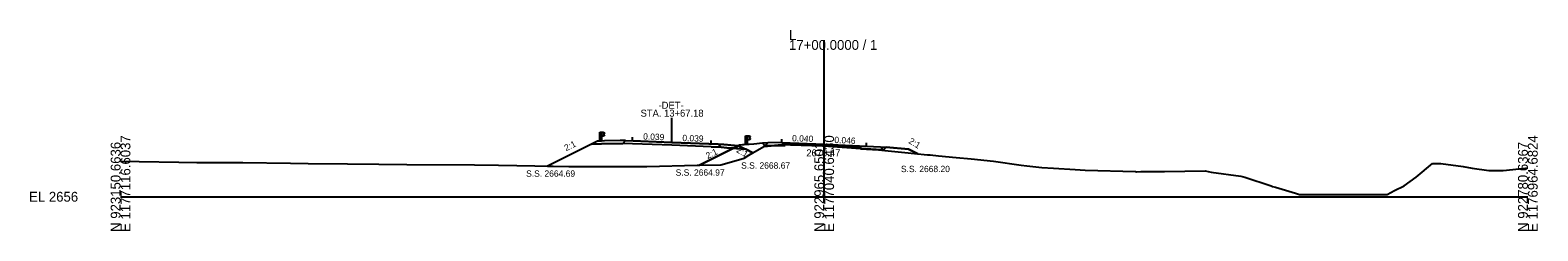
# Model space of a CAD drawing. Extents: x -26 to 1403, y -10 to 9563.
# Drawn here: x -25.7 to 402.8, y 6990.3 to 7047.4 of the extents above; entities that cross this region are included whole.
import ezdxf

# ---------------------------------------------------------------- set-up
doc = ezdxf.new("R2010")
doc.units = 0
for name, color, linetype in [('Exist Cross Section Cell', 7, 'Continuous'), ('Exist XS Center Line Elevation Label', 7, 'Continuous'), ('Exist XS Ground Line', 7, 'Continuous'), ('Prop XS Ditch Slope Text', 7, 'Continuous'), ('Prop XS Dump Level', 7, 'Continuous'), ('Prop XS Earthwork Shape', 7, 'Continuous'), ('Prop XS EOT Tick Mark', 7, 'Continuous'), ('Prop XS Finish Grade', 7, 'Continuous'), ('Prop XS Finish Grade Earthwork', 7, 'Continuous'), ('Prop XS Finish Grade Paved Shoulder', 7, 'Continuous'), ('Prop XS Finish Grade Pavement', 7, 'Continuous'), ('Prop XS Guardrail', 7, 'Continuous'), ('Prop XS Pvmt Edge Slope', 7, 'Continuous'), ('Prop XS SE Text', 7, 'Continuous'), ('Prop XS Shoulder Borrow Shape', 7, 'Continuous'), ('Prop XS Side Slope Text', 7, 'Continuous'), ('Prop XS SS Elevation Text', 7, 'Continuous'), ('Prop XS Subgrade Earthwork', 7, 'Continuous'), ('Prop XS Vertical Lines', 7, 'Continuous'), ('Prop XS Wedging', 7, 'Continuous')]:
    doc.layers.add(name, color=color, linetype=linetype)

msp = doc.modelspace()

# ---------------------------------------------------------------- linework, layer by layer
at = {"layer": 'Exist Cross Section Cell'}
for p, q in [((200, 7000), (200, 7044.56)), ((0, 7000), (200, 7000)), ((200, 7000), (400, 7000))]:
    msp.add_line(p, q, dxfattribs=at)
at = {"layer": 'Exist XS Ground Line'}
for p, q in [((176.35, 7010.73), (177.25, 7011.01)), ((177.25, 7011.01), (178.55, 7011.85)), ((178.55, 7011.85), (179.7, 7012.51)), ((179.7, 7012.51), (182.8, 7014.31)), ((182.8, 7014.31), (187.98, 7014.79)), ((187.98, 7014.79), (188.9, 7014.85)), ((188.9, 7014.85), (190.43, 7014.8)), ((190.43, 7014.8), (199.5, 7014.5)), ((199.5, 7014.5), (200, 7014.47)), ((200, 7014.47), (201.25, 7014.38)), ((201.25, 7014.38), (210.33, 7013.71)), ((210.33, 7013.71), (214.75, 7013.45)), ((214.75, 7013.45), (218.22, 7013.06)), ((218.22, 7013.06), (221.99, 7012.63)), ((221.99, 7012.63), (229.35, 7011.95)), ((229.35, 7011.95), (230.11, 7011.9)), ((230.11, 7011.9), (232.48, 7011.68)), ((232.48, 7011.68), (237.49, 7011.14)), ((237.49, 7011.14), (241.81, 7010.78)), ((0, 7010.07), (5.31, 7009.99)), ((5.31, 7009.99), (16.57, 7009.81)), ((16.57, 7009.81), (21.65, 7009.76)), ((21.65, 7009.76), (34.76, 7009.71)), ((34.76, 7009.71), (48.33, 7009.52)), ((48.33, 7009.52), (53.32, 7009.5)), ((53.32, 7009.5), (64.54, 7009.33)), ((64.54, 7009.33), (73.43, 7009.24)), ((73.43, 7009.24), (81.36, 7009.15)), ((81.36, 7009.15), (100.56, 7009.03)), ((100.56, 7009.03), (107.41, 7008.96)), ((107.41, 7008.96), (122.93, 7008.67)), ((122.93, 7008.67), (127.45, 7008.6)), ((127.45, 7008.6), (129.72, 7008.63)), ((129.72, 7008.63), (149.62, 7008.56)), ((149.62, 7008.56), (163.85, 7008.96)), ((163.85, 7008.96), (170.66, 7009.09)), ((170.66, 7009.09), (176.35, 7010.73)), ((241.81, 7010.78), (248.15, 7010.13)), ((248.15, 7010.13), (256.03, 7008.99)), ((256.03, 7008.99), (257.59, 7008.79)), ((257.59, 7008.79), (261.85, 7008.34)), ((261.85, 7008.34), (265.15, 7008.15)), ((265.15, 7008.15), (271.33, 7007.79)), ((271.33, 7007.79), (274.16, 7007.6)), ((274.16, 7007.6), (288.49, 7007.14)), ((288.49, 7007.14), (288.8, 7007.13)), ((288.8, 7007.13), (289.97, 7007.14)), ((289.97, 7007.14), (296.76, 7007.21)), ((296.76, 7007.21), (308.3, 7007.34)), ((308.3, 7007.34), (309.94, 7007.03)), ((309.94, 7007.03), (318.44, 7005.86)), ((368.27, 7005.58), (372.89, 7009.44)), ((372.89, 7009.44), (375.26, 7009.44)), ((375.26, 7009.44), (381.63, 7008.59)), ((381.63, 7008.59), (384.17, 7008.11)), ((384.17, 7008.11), (388.94, 7007.5)), ((388.94, 7007.5), (393, 7007.46)), ((393, 7007.46), (399.36, 7008.14)), ((399.36, 7008.14), (400, 7008.19)), ((318.44, 7005.86), (319.58, 7005.56)), ((319.58, 7005.56), (327.01, 7003.06)), ((327.01, 7003.06), (327.46, 7002.93)), ((327.46, 7002.93), (328.25, 7002.69)), ((328.25, 7002.69), (333.96, 7001.02)), ((362.11, 7001.76), (364.86, 7003.08)), ((364.86, 7003.08), (368.27, 7005.58)), ((333.96, 7001.02), (335.14, 7000.67)), ((335.14, 7000.67), (347.82, 7000.65)), ((347.82, 7000.65), (353.68, 7000.64)), ((353.68, 7000.64), (359.98, 7000.63)), ((359.98, 7000.63), (362.11, 7001.76))]:
    msp.add_line(p, q, dxfattribs=at)
at = {"layer": 'Prop XS Dump Level'}
for p, q in [((143.54, 7015.98), (156.68, 7015.46)), ((156.68, 7015.46), (145.54, 7015.9)), ((169.82, 7014.94), (156.68, 7015.46)), ((156.68, 7015.46), (169.82, 7014.94)), ((188, 7015.4), (200, 7014.91)), ((200, 7014.91), (212, 7014.36))]:
    msp.add_line(p, q, dxfattribs=at)
at = {"layer": 'Prop XS Earthwork Shape'}
for p, q in [((142.74, 7015.18), (136.74, 7015.05)), ((145.54, 7015.07), (142.74, 7015.18)), ((182.43, 7015.19), (180, 7014.99)), ((183.15, 7014.46), (182.43, 7015.19)), ((133.9, 7014.99), (121.32, 7008.7)), ((136.74, 7015.05), (133.9, 7014.99)), ((156.68, 7014.63), (145.54, 7015.07)), ((167.83, 7014.19), (156.68, 7014.63)), ((164.56, 7008.97), (174.21, 7013.79)), ((174.21, 7013.79), (164.56, 7008.97)), ((174.21, 7013.79), (164.56, 7008.97)), ((170.69, 7014.08), (167.83, 7014.19)), ((172.3, 7013.95), (170.69, 7014.08)), ((174.21, 7013.79), (172.3, 7013.95)), ((177.73, 7013.51), (174.21, 7013.79)), ((177.73, 7013.51), (174.21, 7013.79)), ((175.96, 7014.67), (175.58, 7014.48)), ((175.58, 7014.48), (175.83, 7014.46)), ((175.83, 7014.46), (177.73, 7013.51)), ((176.35, 7010.73), (177.25, 7011.01)), ((176.35, 7010.73), (177.25, 7011.01)), ((177.25, 7011.01), (178.55, 7011.85)), ((177.25, 7011.01), (178.55, 7011.85)), ((179.72, 7012.52), (177.73, 7013.51)), ((179.72, 7012.52), (177.73, 7013.51)), ((177.73, 7013.51), (179.72, 7012.52)), ((178.55, 7011.85), (179.7, 7012.51)), ((178.55, 7011.85), (179.7, 7012.51)), ((179.7, 7012.51), (179.72, 7012.52)), ((179.7, 7012.51), (179.72, 7012.52)), ((179.72, 7012.52), (182.8, 7014.31)), ((182.8, 7014.31), (184.85, 7014.5)), ((184.85, 7014.5), (183.15, 7014.46)), ((216.87, 7013.3), (215.48, 7013.37)), ((215.48, 7013.37), (218.22, 7013.06)), ((217.62, 7014.05), (216.87, 7013.3)), ((223.99, 7013.54), (217.62, 7014.05)), ((218.22, 7013.06), (221.99, 7012.63)), ((221.99, 7012.63), (226.66, 7012.2)), ((226.66, 7012.2), (223.99, 7013.54)), ((121.32, 7008.7), (122.93, 7008.67)), ((122.93, 7008.67), (127.45, 7008.6)), ((127.45, 7008.6), (129.72, 7008.63)), ((129.72, 7008.63), (149.62, 7008.56)), ((149.62, 7008.56), (163.85, 7008.96)), ((163.85, 7008.96), (164.56, 7008.97)), ((164.56, 7008.97), (170.66, 7009.09)), ((164.56, 7008.97), (170.66, 7009.09)), ((170.66, 7009.09), (176.35, 7010.73)), ((170.66, 7009.09), (176.35, 7010.73))]:
    msp.add_line(p, q, dxfattribs=at)
msp.add_lwpolyline([(180, 7014.99), (178.14, 7014.85), (177.64, 7014.81), (175.96, 7014.67)], dxfattribs=at)
at = {"layer": 'Prop XS EOT Tick Mark'}
for p, q in [((145.54, 7015.9), (145.54, 7016.9)), ((167.83, 7015.02), (167.83, 7016.02)), ((188, 7015.4), (188, 7016.4)), ((212, 7014.36), (212, 7015.36))]:
    msp.add_line(p, q, dxfattribs=at)
at = {"layer": 'Prop XS Finish Grade'}
for p, q in [((143.54, 7015.98), (141.97, 7015.95)), ((184, 7015.32), (182.43, 7015.19)), ((169.82, 7014.94), (171.43, 7014.81)), ((216, 7014.18), (217.62, 7014.05))]:
    msp.add_line(p, q, dxfattribs=at)
at = {"layer": 'Prop XS Finish Grade Earthwork'}
for p, q in [((135.54, 7015.81), (133.9, 7014.99)), ((137.54, 7015.86), (135.54, 7015.81)), ((141.97, 7015.95), (137.54, 7015.86)), ((182.43, 7015.19), (180, 7014.99)), ((133.9, 7014.99), (121.32, 7008.7)), ((175.96, 7014.67), (164.56, 7008.97)), ((171.43, 7014.81), (175.83, 7014.46)), ((175.83, 7014.46), (177.73, 7013.51)), ((180, 7014.99), (175.96, 7014.67)), ((177.73, 7013.51), (179.72, 7012.52)), ((217.62, 7014.05), (223.99, 7013.54)), ((223.99, 7013.54), (226.66, 7012.2))]:
    msp.add_line(p, q, dxfattribs=at)
at = {"layer": 'Prop XS Finish Grade Paved Shoulder'}
for p, q in [((188, 7015.4), (184, 7015.32)), ((212, 7014.36), (216, 7014.18))]:
    msp.add_line(p, q, dxfattribs=at)
at = {"layer": 'Prop XS Finish Grade Pavement'}
for p, q in [((143.54, 7015.98), (156.68, 7015.46)), ((156.68, 7015.46), (169.82, 7014.94)), ((188, 7015.4), (200, 7014.91)), ((200, 7014.91), (212, 7014.36))]:
    msp.add_line(p, q, dxfattribs=at)
at = {"layer": 'Prop XS Guardrail'}
for p, q in [((136.22, 7018.34), (136.72, 7018.34)), ((136.22, 7015.84), (136.22, 7018.34)), ((136.72, 7018.34), (137.22, 7018.34)), ((136.72, 7018.34), (136.72, 7015.84)), ((137.22, 7017.2), (136.72, 7017.2)), ((137.22, 7018.34), (137.51, 7018.14)), ((137.51, 7018.02), (137.22, 7017.82)), ((137.22, 7017.82), (137.22, 7017.72)), ((137.22, 7017.72), (137.51, 7017.52)), ((137.51, 7017.4), (137.22, 7017.2)), ((137.51, 7018.14), (137.54, 7018.08)), ((137.54, 7018.08), (137.51, 7018.02)), ((137.51, 7017.52), (137.54, 7017.46)), ((137.54, 7017.46), (137.51, 7017.4)), ((177.64, 7017.35), (178.14, 7017.35)), ((177.64, 7014.81), (177.64, 7017.35)), ((178.14, 7017.35), (178.64, 7017.35)), ((178.14, 7017.35), (178.14, 7014.85)), ((178.64, 7016.21), (178.14, 7016.21)), ((178.64, 7017.35), (178.93, 7017.15)), ((178.93, 7017.03), (178.64, 7016.83)), ((178.64, 7016.83), (178.64, 7016.73)), ((178.64, 7016.73), (178.93, 7016.53)), ((178.93, 7016.41), (178.64, 7016.21)), ((178.93, 7017.15), (178.96, 7017.09)), ((178.96, 7017.09), (178.93, 7017.03)), ((178.93, 7016.53), (178.96, 7016.47)), ((178.96, 7016.47), (178.93, 7016.41))]:
    msp.add_line(p, q, dxfattribs=at)
at = {"layer": 'Prop XS Pvmt Edge Slope'}
for p, q in [((143.54, 7015.98), (142.74, 7015.18)), ((184, 7015.32), (183.15, 7014.46)), ((169.82, 7014.94), (170.69, 7014.08)), ((216, 7014.18), (216.87, 7013.3))]:
    msp.add_line(p, q, dxfattribs=at)
at = {"layer": 'Prop XS Shoulder Borrow Shape'}
for p, q in [((135.54, 7015.81), (133.9, 7014.99)), ((136.74, 7015.05), (142.74, 7015.18)), ((141.97, 7015.95), (137.54, 7015.86)), ((143.54, 7015.98), (141.97, 7015.95)), ((142.74, 7015.18), (143.54, 7015.98)), ((133.9, 7014.99), (136.74, 7015.05)), ((171.43, 7014.81), (169.82, 7014.94)), ((169.82, 7014.94), (170.69, 7014.08)), ((170.69, 7014.08), (172.3, 7013.95)), ((175.58, 7014.48), (171.43, 7014.81)), ((172.3, 7013.95), (174.21, 7013.79)), ((174.21, 7013.79), (175.58, 7014.48))]:
    msp.add_line(p, q, dxfattribs=at)
msp.add_lwpolyline([(137.54, 7015.86), (136.72, 7015.84), (135.54, 7015.81)], dxfattribs=at)
at = {"layer": 'Prop XS Subgrade Earthwork'}
for p, q in [((142.74, 7015.18), (136.74, 7015.05)), ((145.54, 7015.07), (142.74, 7015.18)), ((183.15, 7014.46), (182.43, 7015.19)), ((136.74, 7015.05), (133.9, 7014.99)), ((156.68, 7014.63), (145.54, 7015.07)), ((167.83, 7014.19), (156.68, 7014.63)), ((167.83, 7014.19), (170.69, 7014.08)), ((170.69, 7014.08), (172.3, 7013.95)), ((172.3, 7013.95), (177.73, 7013.51)), ((188, 7014.56), (183.15, 7014.46)), ((188, 7014.56), (188.9, 7014.53)), ((188.9, 7014.53), (188.9, 7014.85)), ((210.33, 7013.6), (210.33, 7013.71)), ((210.33, 7013.6), (216.87, 7013.3)), ((216.87, 7013.3), (217.62, 7014.05))]:
    msp.add_line(p, q, dxfattribs=at)
at = {"layer": 'Prop XS Vertical Lines'}
msp.add_line((156.68, 7015.46), (156.68, 7022.46), dxfattribs=at)
at = {"layer": 'Prop XS Wedging'}
for p, q in [((187.98, 7014.79), (184.85, 7014.5)), ((184.85, 7014.5), (188, 7014.56)), ((188.9, 7014.85), (187.98, 7014.79)), ((188, 7014.56), (188.9, 7014.53)), ((188.9, 7014.53), (188.9, 7014.85)), ((214.75, 7013.45), (210.33, 7013.71)), ((210.33, 7013.71), (210.33, 7013.6)), ((210.33, 7013.6), (215.48, 7013.37)), ((215.48, 7013.37), (214.75, 7013.45))]:
    msp.add_line(p, q, dxfattribs=at)
msp.add_lwpolyline([(188.9, 7014.85), (188.9, 7015.16), (190.43, 7015.09), (199.5, 7014.73), (200, 7014.71), (200.55, 7014.69), (201.25, 7014.65), (210.33, 7014.2), (210.33, 7013.71), (201.25, 7014.38), (200.55, 7014.43), (200, 7014.47), (199.5, 7014.5), (190.43, 7014.8)], close=True, dxfattribs=at)
msp.add_lwpolyline([(188.9, 7014.85), (188.9, 7015.16), (190.43, 7015.09), (199.5, 7014.73), (200, 7014.71), (200.55, 7014.69), (201.25, 7014.65), (210.33, 7014.2), (210.33, 7013.71), (201.25, 7014.38), (200.55, 7014.43), (200, 7014.47), (199.5, 7014.5), (190.43, 7014.8)], close=True, dxfattribs=at)

# ---------------------------------------------------------------- texts
at = {"layer": 'Exist Cross Section Cell'}
for s, p in [('L', (190, 7044.56)), ('17+00.0000 / 1', (190, 7041.76)), ('EL 2656', (-26, 6998.6))]:
    msp.add_text(s, height=2.8, dxfattribs=at).set_placement(p)
for s, p in [('N 923150.6636', (0, 6990)), ('E 1177116.6037', (2.8, 6990)), ('N 922965.6501', (200, 6990)), ('E 1177040.6430', (202.8, 6990)), ('N 922780.6367', (400, 6990)), ('E 1176964.6824', (402.8, 6990))]:
    msp.add_text(s, height=2.8, rotation=90, dxfattribs=at).set_placement(p)
at = {"layer": 'Exist XS Center Line Elevation Label'}
msp.add_text('2670.47', height=2, dxfattribs=at).set_placement((194.91, 7011.47))
at = {"layer": 'Prop XS Ditch Slope Text'}
for rotation, p in [(328.6038, (223.83, 7015.35)), (330.7002, (174.85, 7012.76))]:
    msp.add_text('2:1', height=1.8, rotation=rotation, dxfattribs=at).set_placement(p)
at = {"layer": 'Prop XS Dump Level'}
for s, p in [('Case1', (137.54, 7015.7)), ('Case1', (175.83, 7014.34)), ('Case2', (180, 7014.95)), ('Case2', (220, 7013.82))]:
    msp.add_text(s, height=0.04, dxfattribs=at).set_placement(p)
at = {"layer": 'Prop XS SE Text'}
for s, rotation, p in [('0.039', 357.7448, (148.51, 7016.28)), ('0.039', 357.7432, (159.66, 7015.84)), ('0.040', 357.7094, (190.84, 7015.78)), ('0.046', 357.3554, (202.86, 7015.28))]:
    msp.add_text(s, height=1.8, rotation=rotation, dxfattribs=at).set_placement(p)
at = {"layer": 'Prop XS Side Slope Text'}
for p in [(126.66, 7012.93), (166.89, 7010.7)]:
    msp.add_text('2:1', height=1.8, rotation=26.5651, dxfattribs=at).set_placement(p)
at = {"layer": 'Prop XS SS Elevation Text'}
for s, p in [('S.S. 2664.69', (115.28, 7005.69)), ('S.S. 2664.97', (157.78, 7005.99)), ('S.S. 2668.67', (176.39, 7007.99)), ('S.S. 2668.20', (221.81, 7007))]:
    msp.add_text(s, height=1.8, dxfattribs=at).set_placement(p)
at = {"layer": 'Prop XS Vertical Lines'}
for s, p in [('STA. 13+67.18', (147.8, 7022.76)), ('-DET-', (152.92, 7025.01))]:
    msp.add_text(s, height=2, dxfattribs=at).set_placement(p)

doc.saveas('drawing.dxf')
